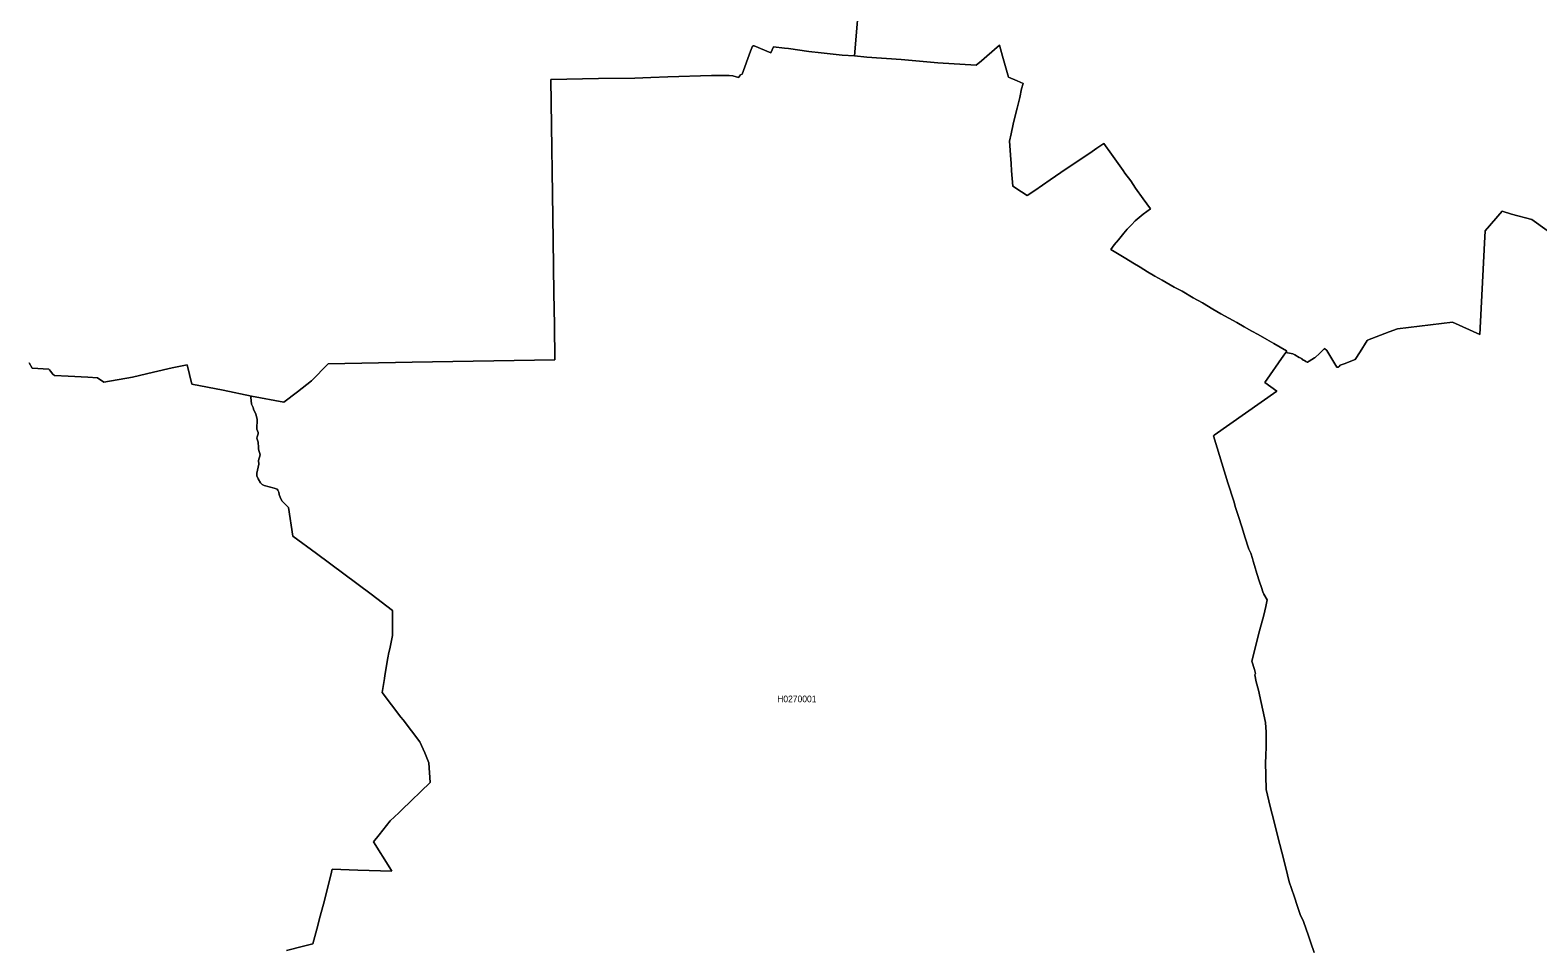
# Model space of a CAD drawing. Extents: x 369010 to 739155, y 6377141 to 6616555.
# Drawn here: x 399245 to 421785, y 6469046 to 6482767 of the extents above; entities that cross this region are included whole.
import ezdxf
from ezdxf.enums import TextEntityAlignment as Align

# ---------------------------------------------------------------- set-up
doc = ezdxf.new("R2010")
doc.units = 0
doc.header["$LTSCALE"] = 40
doc.layers.add('1', color=7, linetype='Continuous', lineweight=13)
doc.layers.add('2', color=7, linetype='Continuous')

msp = doc.modelspace()

# ---------------------------------------------------------------- linework, layer by layer
at = {"layer": '1'}
for points in [[(399227.76, 6477791.58), (399273.94, 6477711.81), (399523.68, 6477698.9), (399536.43, 6477690.13), (399550.82, 6477667.62), (399581.44, 6477623.6), (399608.09, 6477606.22), (399812.32, 6477593.47), (400105.76, 6477579.57), (400250.08, 6477570.8), (400345.57, 6477503.11), (400773.4, 6477577.75), (401087.36, 6477655.7), (401369.55, 6477719.92), (401593.31, 6477762.29), (401661.5, 6477475.14), (402128.72, 6477383.12), (402555.38, 6477292.42), (403039.15, 6477204.87), (403243.38, 6477358.46), (403451.42, 6477523.13), (403702.16, 6477779.5), (404955.52, 6477804.49), (407090.86, 6477838.92), (407083.9, 6478359.59), (407074.47, 6478836.74), (407063.38, 6479626.52), (407029.95, 6482031.13), (407739.63, 6482044.37), (408283.97, 6482049.67), (408525.78, 6482058.94), (408779.49, 6482069.36), (409431.58, 6482089.06), (409694.07, 6482090.88), (409747.86, 6482086.41), (409836.73, 6482061.42), (409866.19, 6482098.16), (409888.54, 6482110.57), (410012, 6482454.99), (410044.77, 6482530.29), (410052.55, 6482532.61), (410067.11, 6482531.12), (410317.52, 6482429.5), (410358.9, 6482519.2), (410520.43, 6482498.85), (410584.48, 6482490.9), (410887.52, 6482450.19), (411073.05, 6482426.19), (411382.37, 6482395.41), (411571.05, 6482381.5), (411655.95, 6483395.71)], [(411655.95, 6483395.71), (411571.05, 6482381.5), (411754.26, 6482363.13), (412265.01, 6482329.21), (412815.14, 6482280.88), (413388.78, 6482242.81), (413465.57, 6482307.36), (413548.49, 6482378.19), (413737.33, 6482542.37), (413783.67, 6482379.85), (413870.23, 6482063.74), (414000.98, 6482010.28), (414090.52, 6481971.55), (414068.01, 6481889.3), (414038.71, 6481762.52), (413999.99, 6481599.17), (413963.41, 6481445.58), (413943.38, 6481362.33), (413908.96, 6481219.17), (413884.13, 6481108.45), (413889.26, 6481042.74), (413900.68, 6480898.09), (413908.96, 6480773.96), (413918.56, 6480662.41), (413927.33, 6480547.06), (413935.94, 6480433.36), (414067.84, 6480351.1), (414148.44, 6480297.48), (414263.8, 6480371.79), (414495.01, 6480530.01), (414734, 6480692.04), (415085.2, 6480928.54), (415191.95, 6481000.7), (415294.72, 6481071.04), (415411.9, 6480911.17), (415485.88, 6480809.71), (415587, 6480669.86), (415612.99, 6480631.13), (415697.89, 6480516.61), (415769.55, 6480406.05), (415882.92, 6480243.69), (415993.48, 6480095.89), (415887.06, 6480017.94), (415766.74, 6479916.49), (415707.99, 6479858.89), (415647.58, 6479791.86), (415596.27, 6479730.96), (415516.5, 6479630.33), (415451.95, 6479555.03), (415402.14, 6479490.15), (415625.23, 6479354.27), (415731.82, 6479288.4), (415841.05, 6479222.2), (415950.45, 6479155.67), (416057.37, 6479088.97), (416168.42, 6479026.74), (416348.65, 6478925.78), (416465.33, 6478862.56)], [(411571.05, 6482381.5), (411382.37, 6482395.41), (411073.05, 6482426.19), (410887.52, 6482450.19), (410584.48, 6482490.9), (410520.43, 6482498.85), (410358.9, 6482519.2), (410317.52, 6482429.5), (410067.11, 6482531.12), (410052.55, 6482532.61), (410044.77, 6482530.29), (410012, 6482454.99), (409888.54, 6482110.57), (409866.19, 6482098.16), (409836.73, 6482061.42), (409747.86, 6482086.41), (409694.07, 6482090.88), (409431.58, 6482089.06), (408779.49, 6482069.36), (408525.78, 6482058.94), (408283.97, 6482049.67), (407739.63, 6482044.37), (407029.95, 6482031.13), (407063.38, 6479626.52), (407074.47, 6478836.74), (407083.9, 6478359.59), (407090.86, 6477838.92), (404955.52, 6477804.49), (403702.16, 6477779.5), (403451.42, 6477523.13), (403243.38, 6477358.46), (403039.15, 6477204.87), (402555.38, 6477292.42), (402544.46, 6477282.16), (402552.57, 6477174.91), (402578.89, 6477122.95), (402583.19, 6477101.1), (402619.27, 6477023.15), (402640.78, 6476949), (402633.5, 6476800.88), (402653.69, 6476751.06), (402652.87, 6476731.2), (402637.47, 6476686.84), (402633.5, 6476668.14), (402642.77, 6476635.87), (402651.54, 6476604.75), (402657.67, 6476528.62), (402656.51, 6476504.79), (402681.5, 6476419.72), (402659.98, 6476333.82), (402663.29, 6476278.71), (402655.85, 6476231.04), (402631.35, 6476143.49), (402632.67, 6476103.11), (402654.02, 6476058.59), (402686.96, 6475999.67), (402711.95, 6475973.02), (402741.58, 6475956.97), (402891.85, 6475919.73), (402935.71, 6475905.17), (402948.79, 6475889.78), (402962.19, 6475858.83), (402965.83, 6475823.9), (402986.36, 6475769.62), (403014.66, 6475724.6), (403105.85, 6475630.76), (403169.9, 6475200.62), (403524.74, 6474942.1), (404342.5, 6474333.21), (404660.93, 6474090.58), (404661.75, 6473716.38), (404622.53, 6473519.26), (404607.14, 6473461.5), (404593.24, 6473382.39), (404548.55, 6473119.24), (404540.6, 6473071.41), (404506.35, 6472866.02), (404788.86, 6472496.45), (404820.47, 6472454.91), (405068.56, 6472124.56), (405147.34, 6471961.04), (405206.76, 6471812.75), (405225.46, 6471518.15), (404802.1, 6471107.54), (404756.26, 6471066.99), (404626.17, 6470946.17), (404463.98, 6470734.99), (404378.08, 6470629.07), (404621.87, 6470243.61), (404649.84, 6470192.8), (404141.41, 6470210.01), (403758.1, 6470220.6), (403739.23, 6470131.89), (403631.33, 6469700.09), (403595.91, 6469573.81), (403582.01, 6469521.02), (403530.86, 6469325.89), (403516.3, 6469270.28), (403472.77, 6469107.26), (403331.43, 6469070.68)], [(415647.58, 6479791.86), (415707.99, 6479858.89), (415766.74, 6479916.49), (415887.06, 6480017.94), (415993.48, 6480095.89), (415882.92, 6480243.69), (415769.55, 6480406.05), (415697.89, 6480516.61), (415612.99, 6480631.13), (415587, 6480669.86), (415485.88, 6480809.71), (415411.9, 6480911.17), (415294.72, 6481071.04), (415191.95, 6481000.7), (415085.2, 6480928.54), (414734, 6480692.04), (414495.01, 6480530.01), (414263.8, 6480371.79), (414148.44, 6480297.48), (414067.84, 6480351.1), (413935.94, 6480433.36), (413927.33, 6480547.06), (413918.56, 6480662.41), (413908.96, 6480773.96), (413900.68, 6480898.09), (413889.26, 6481042.74), (413884.13, 6481108.45), (413908.96, 6481219.17), (413943.38, 6481362.33), (413963.41, 6481445.58), (413999.99, 6481599.17), (414038.71, 6481762.52), (414068.01, 6481889.3), (414090.52, 6481971.55), (414000.98, 6482010.28), (413870.23, 6482063.74), (413783.67, 6482379.85), (413737.33, 6482542.37), (413548.49, 6482378.19), (413465.57, 6482307.36), (413388.78, 6482242.81), (412815.14, 6482280.88), (412265.01, 6482329.21), (411754.26, 6482363.13), (411571.05, 6482381.5)], [(416465.33, 6478862.56), (416633.49, 6478766.4), (416770.19, 6478688.94), (416926.43, 6478597.42), (417046.58, 6478527.41), (417163.26, 6478462.04), (417283.09, 6478394.02), (417393.15, 6478330.46), (417508.5, 6478267.74), (417601.52, 6478215.44), (417731.44, 6478141.95), (417839.02, 6478080.55), (418029.84, 6477972.48), (418031.17, 6477969.17), (418017.1, 6477948.81), (418026.04, 6477946.99), (418043.08, 6477941.86), (418071.88, 6477935.24), (418120.87, 6477925.47), (418130.8, 6477922.33), (418151.49, 6477912.07), (418218.85, 6477872.51), (418220.17, 6477874.66), (418260.39, 6477851.49), (418259.07, 6477849.34), (418284.06, 6477834.28), (418292.17, 6477829.48), (418297.63, 6477826.67), (418317.98, 6477813.93), (418337.35, 6477802.17), (418342.31, 6477802.51), (418367.64, 6477818.23), (418447.24, 6477869.53), (418449.06, 6477867.05), (418523.87, 6477939.54), (418594.71, 6478008.56), (418628.8, 6477975.29), (418782.55, 6477728.69), (418790.33, 6477727.7), (418803.24, 6477730.68), (418813.17, 6477736.97), (418830.39, 6477756.5), (418888.97, 6477776.85), (419051.83, 6477843.22), (419127.96, 6477958.74), (419233.72, 6478126.56), (419239.68, 6478131.2), (419432.82, 6478206.83), (419564.23, 6478257.31), (419687.03, 6478303.82), (420511.41, 6478401.3), (420919.87, 6478217.26), (420987.07, 6479582.67), (420996.17, 6479766.87), (421253.03, 6480063.12), (421391.23, 6480016.78), (421695.09, 6479933.87), (422451.12, 6479393.83)], [(422451.12, 6479393.83), (421695.09, 6479933.87), (421391.23, 6480016.78), (421253.03, 6480063.12), (420996.17, 6479766.87), (420987.07, 6479582.67), (420919.87, 6478217.26), (420511.41, 6478401.3), (419687.03, 6478303.82), (419564.23, 6478257.31), (419432.82, 6478206.83), (419239.68, 6478131.2), (419233.72, 6478126.56), (419127.96, 6477958.74), (419051.83, 6477843.22), (418888.97, 6477776.85), (418830.39, 6477756.5), (418813.17, 6477736.97), (418803.24, 6477730.68), (418790.33, 6477727.7), (418782.55, 6477728.69), (418628.8, 6477975.29), (418594.71, 6478008.56), (418523.87, 6477939.54), (418449.06, 6477867.05), (418447.24, 6477869.53)], [(418438.97, 6468977.17), (418393.79, 6469120.83), (418356.71, 6469227.08), (418281.08, 6469438.93), (418232.25, 6469543.52), (418187.4, 6469678.74), (418144.87, 6469806.01), (418100.68, 6469934.61), (418067.25, 6470032.26), (418018.42, 6470243.44), (417955.37, 6470477.46), (417899.26, 6470704.7), (417842, 6470932.27), (417781.42, 6471161.33), (417723.83, 6471415.71), (417714.23, 6471822.18), (417717.37, 6471906.26), (417723.33, 6472068.29), (417722.83, 6472270.87), (417715.05, 6472414.36), (417607.81, 6472896.97), (417572.06, 6473025.23), (417552.03, 6473129.17), (417562.13, 6473148.7), (417548.23, 6473209.11), (417508.67, 6473330.59), (417625.68, 6473786.72), (417687.91, 6474020.08), (417716.54, 6474150.49), (417737.89, 6474249.3), (417687.91, 6474335.36), (417673.51, 6474368.3), (417651.33, 6474436.15), (417625.68, 6474520.4), (417584.31, 6474645.52), (417548.23, 6474762.69), (417529.69, 6474826.25), (417520.26, 6474868.78), (417494.11, 6474948.72), (417465.97, 6475006.98), (417405.89, 6475192.51), (417363.36, 6475324.58), (417304.44, 6475509.94), (417266.21, 6475632.58), (417238.4, 6475723.78), (417151.51, 6475997.35), (416938.67, 6476703.56), (416946.12, 6476711.01), (417881.88, 6477371.04), (417702.64, 6477497.65), (417988.3, 6477907.27), (418017.1, 6477948.81), (418031.17, 6477969.17), (418029.84, 6477972.48), (417839.02, 6478080.55), (417731.44, 6478141.95), (417601.52, 6478215.44), (417508.5, 6478267.74), (417393.15, 6478330.46), (417283.09, 6478394.02), (417163.26, 6478462.04), (417046.58, 6478527.41), (416926.43, 6478597.42), (416770.19, 6478688.94), (416633.49, 6478766.4), (416465.33, 6478862.56), (416348.65, 6478925.78), (416168.42, 6479026.74), (416057.37, 6479088.97), (415950.45, 6479155.67), (415841.05, 6479222.2), (415731.82, 6479288.4), (415625.23, 6479354.27), (415402.14, 6479490.15), (415451.95, 6479555.03), (415516.5, 6479630.33), (415596.27, 6479730.96), (415647.58, 6479791.86)], [(418447.24, 6477869.53), (418367.64, 6477818.23), (418342.31, 6477802.51), (418337.35, 6477802.17), (418317.98, 6477813.93), (418297.63, 6477826.67), (418292.17, 6477829.48), (418284.06, 6477834.28), (418259.07, 6477849.34), (418260.39, 6477851.49), (418220.17, 6477874.66), (418218.85, 6477872.51), (418151.49, 6477912.07), (418130.8, 6477922.33), (418120.87, 6477925.47), (418071.88, 6477935.24), (418043.08, 6477941.86), (418026.04, 6477946.99), (418017.1, 6477948.81), (417988.3, 6477907.27), (417702.64, 6477497.65), (417881.88, 6477371.04), (416946.12, 6476711.01), (416938.67, 6476703.56), (417151.51, 6475997.35), (417238.4, 6475723.78), (417266.21, 6475632.58), (417304.44, 6475509.94), (417363.36, 6475324.58), (417405.89, 6475192.51), (417465.97, 6475006.98), (417494.11, 6474948.72), (417520.26, 6474868.78), (417529.69, 6474826.25), (417548.23, 6474762.69), (417584.31, 6474645.52), (417625.68, 6474520.4), (417651.33, 6474436.15), (417673.51, 6474368.3), (417687.91, 6474335.36), (417737.89, 6474249.3), (417716.54, 6474150.49), (417687.91, 6474020.08), (417625.68, 6473786.72), (417508.67, 6473330.59), (417548.23, 6473209.11), (417562.13, 6473148.7), (417552.03, 6473129.17), (417572.06, 6473025.23), (417607.81, 6472896.97), (417715.05, 6472414.36), (417722.83, 6472270.87), (417723.33, 6472068.29), (417717.37, 6471906.26), (417714.23, 6471822.18), (417723.83, 6471415.71), (417781.42, 6471161.33), (417842, 6470932.27), (417899.26, 6470704.7), (417955.37, 6470477.46), (418018.42, 6470243.44), (418067.25, 6470032.26), (418100.68, 6469934.61), (418144.87, 6469806.01), (418187.4, 6469678.74), (418232.25, 6469543.52), (418281.08, 6469438.93), (418356.71, 6469227.08), (418393.79, 6469120.83), (418438.97, 6468977.17)], [(402965.83, 6475823.9), (402962.19, 6475858.83), (402948.79, 6475889.78), (402935.71, 6475905.17), (402891.85, 6475919.73), (402741.58, 6475956.97), (402711.95, 6475973.02), (402686.96, 6475999.67), (402654.02, 6476058.59), (402632.67, 6476103.11), (402631.35, 6476143.49), (402655.85, 6476231.04), (402663.29, 6476278.71), (402659.98, 6476333.82), (402681.5, 6476419.72), (402656.51, 6476504.79), (402657.67, 6476528.62), (402651.54, 6476604.75), (402642.77, 6476635.87), (402633.5, 6476668.14), (402637.47, 6476686.84), (402652.87, 6476731.2), (402653.69, 6476751.06), (402633.5, 6476800.88), (402640.78, 6476949), (402619.27, 6477023.15), (402583.19, 6477101.1), (402578.89, 6477122.95), (402552.57, 6477174.91), (402544.46, 6477282.16), (402555.38, 6477292.42), (402128.72, 6477383.12), (401661.5, 6477475.14), (401593.31, 6477762.29), (401369.55, 6477719.92), (401087.36, 6477655.7), (400773.4, 6477577.75), (400345.57, 6477503.11), (400250.08, 6477570.8), (400105.76, 6477579.57), (399812.32, 6477593.47), (399608.09, 6477606.22), (399581.44, 6477623.6), (399550.82, 6477667.62), (399536.43, 6477690.13), (399523.68, 6477698.9), (399273.94, 6477711.81), (399227.76, 6477791.58)], [(403074.9, 6469008.78), (403331.43, 6469070.68), (403472.77, 6469107.26), (403516.3, 6469270.28), (403530.86, 6469325.89), (403582.01, 6469521.02), (403595.91, 6469573.81), (403631.33, 6469700.09), (403739.23, 6470131.89), (403758.1, 6470220.6), (404141.41, 6470210.01), (404649.84, 6470192.8), (404621.87, 6470243.61), (404378.08, 6470629.07), (404463.98, 6470734.99), (404626.17, 6470946.17), (404756.26, 6471066.99), (404802.1, 6471107.54), (405225.46, 6471518.15), (405206.76, 6471812.75), (405147.34, 6471961.04), (405068.56, 6472124.56), (404820.47, 6472454.91), (404788.86, 6472496.45), (404506.35, 6472866.02), (404540.6, 6473071.41), (404548.55, 6473119.24), (404593.24, 6473382.39), (404607.14, 6473461.5), (404622.53, 6473519.26), (404661.75, 6473716.38), (404660.93, 6474090.58), (404342.5, 6474333.21), (403524.74, 6474942.1), (403169.9, 6475200.62), (403105.85, 6475630.76), (403014.66, 6475724.6), (402986.36, 6475769.62), (402965.83, 6475823.9)], [(403331.43, 6469070.68), (403074.9, 6469008.78)]]:
    msp.add_lwpolyline(points, dxfattribs=at)

# ---------------------------------------------------------------- texts
at = {"layer": '2', "width": 0.95}
msp.add_text('H0270001', height=100, dxfattribs=at).set_placement((410706.85, 6472718.36), align=Align.CENTER)

doc.saveas('drawing.dxf')
